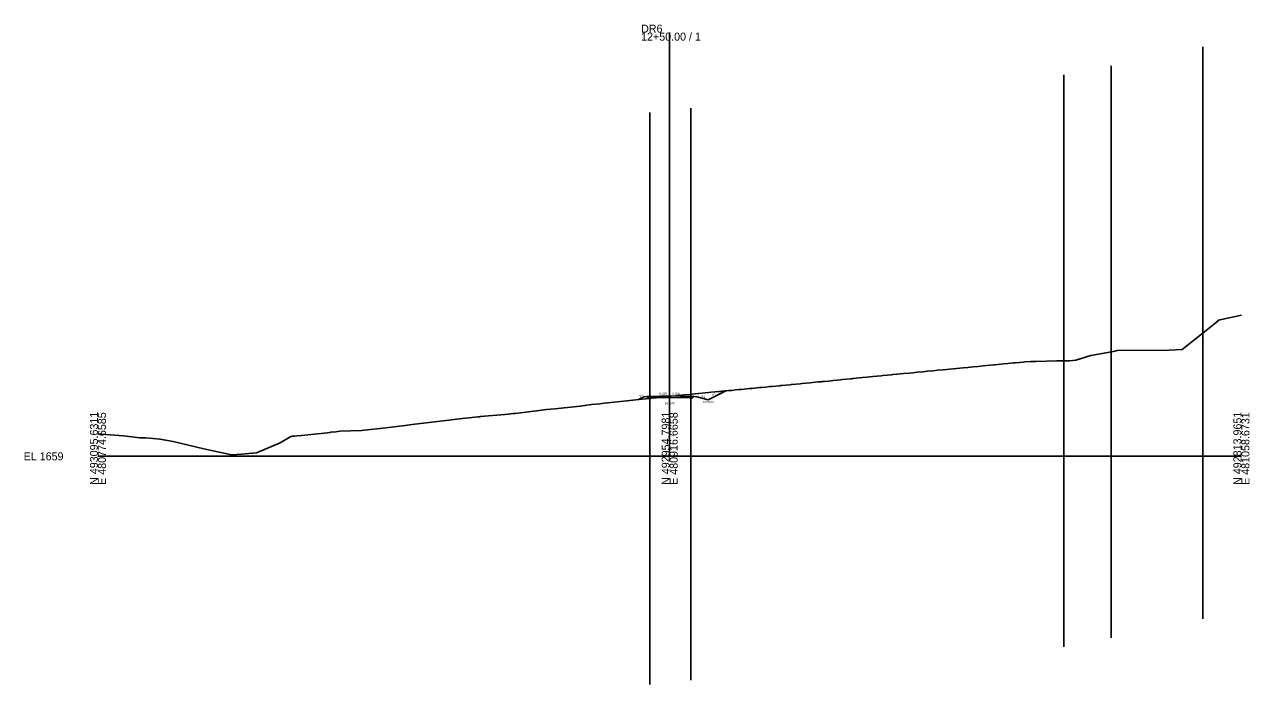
# Model space of a CAD drawing. Extents: x -26 to 403, y -88 to 5647.
# Drawn here: x -25.7 to 402.8, y 4920.2 to 5151 of the extents above; entities that cross this region are included whole.
import ezdxf

# ---------------------------------------------------------------- set-up
doc = ezdxf.new("R2010")
doc.units = 0
for name, color, linetype in [('Exist Cross Section Cell', 7, 'Continuous'), ('Exist XS Center Line Elevation Label', 7, 'Continuous'), ('Exist XS Ground Line', 7, 'Continuous'), ('Prop Road Sect_ Boring - Material (Outline)', 7, 'Continuous'), ('Prop XS Ditch Slope Text', 7, 'Continuous'), ('Prop XS Ditch Standard Text', 7, 'Continuous'), ('Prop XS Dump Level', 7, 'Continuous'), ('Prop XS Earthwork Shape', 7, 'Continuous'), ('Prop XS EOT Tick Mark', 7, 'Continuous'), ('Prop XS Finish Grade', 7, 'Continuous'), ('Prop XS Finish Grade Earthwork', 7, 'Continuous'), ('Prop XS Finish Grade Pavement', 7, 'Continuous'), ('Prop XS Hydro Typical Ditch Data', 7, 'Continuous'), ('Prop XS Pvmt Edge Slope', 7, 'Continuous'), ('Prop XS SE Text', 7, 'Continuous'), ('Prop XS Side Slope Text', 7, 'Continuous'), ('Prop XS Subgrade Earthwork', 7, 'Continuous'), ('Scratch_Level_7', 7, 'Continuous')]:
    doc.layers.add(name, color=color, linetype=linetype)

msp = doc.modelspace()

# ---------------------------------------------------------------- linework, layer by layer
at = {"layer": 'Exist Cross Section Cell'}
for p, q in [((200, 5000), (200, 5148.14)), ((0, 5000), (200, 5000)), ((200, 5000), (400, 5000))]:
    msp.add_line(p, q, dxfattribs=at)
at = {"layer": 'Exist XS Ground Line'}
msp.add_lwpolyline([(0, 5007.85), (2.77, 5007.6), (8.96, 5007.12), (14.66, 5006.5), (16.8, 5006.44), (21.67, 5006.03), (26.28, 5005.24), (37.04, 5002.65), (46.73, 5000.51), (47.11, 5000.53), (50.22, 5000.75), (51.5, 5000.84), (55.46, 5001.19), (63.72, 5004.67), (67.46, 5006.95), (67.96, 5007.04), (68.75, 5007.04), (69.71, 5007.13), (71.22, 5007.32), (80.3, 5008.27), (81.15, 5008.38), (81.52, 5008.42), (83.27, 5008.61), (84.6, 5008.77), (92.18, 5009.07), (100.71, 5010.02), (107.44, 5010.82), (109.92, 5011.15), (123.64, 5012.78), (125.39, 5012.97), (132.86, 5013.8), (133.18, 5013.83), (133.51, 5013.86), (133.83, 5013.9), (142.32, 5014.66), (143.66, 5014.79), (145.31, 5014.96), (146, 5015.02), (154.38, 5016.07), (156.97, 5016.32), (159.9, 5016.62), (163.1, 5016.94), (168.75, 5017.55), (172.61, 5018.11), (175.53, 5018.4), (177.09, 5018.56), (180.56, 5018.93), (185.05, 5019.4), (188.11, 5019.78), (189.32, 5019.88), (189.89, 5019.93), (190.29, 5019.97), (191.66, 5020.1), (193.08, 5020.23), (194.74, 5020.41), (196.98, 5020.63), (198.18, 5020.73), (199.42, 5020.88), (200, 5020.94), (200.56, 5021), (202.17, 5021.15), (202.98, 5021.24), (203.54, 5021.29), (204.06, 5021.36), (205.24, 5021.47), (207.16, 5021.66), (207.85, 5021.73), (208.9, 5021.84), (209.92, 5021.94), (210.25, 5021.98), (211.36, 5022.08), (212.45, 5022.18), (213.54, 5022.29), (214.56, 5022.39), (215.91, 5022.52), (217.21, 5022.64), (217.62, 5022.68), (218.14, 5022.73), (220.72, 5022.98), (221.72, 5023.07), (223.01, 5023.2), (224.29, 5023.32), (225.3, 5023.42), (227.83, 5023.67), (228.74, 5023.75), (231.43, 5024.02), (231.82, 5024.06), (232.25, 5024.1), (233.63, 5024.23), (234.98, 5024.36), (235.83, 5024.44), (238.52, 5024.7), (238.9, 5024.74), (239.28, 5024.78), (240.67, 5024.91), (242.04, 5025.04), (242.46, 5025.08), (242.89, 5025.12), (245.62, 5025.38), (246.35, 5025.45), (247.71, 5025.58), (249.16, 5025.72), (249.92, 5025.79), (252, 5025.99), (252.7, 5026.06), (253.05, 5026.09), (253.4, 5026.13), (254.14, 5026.2), (255.44, 5026.33), (256.46, 5026.43), (257.18, 5026.5), (258.63, 5026.64), (259.78, 5026.75), (260.48, 5026.82), (263.37, 5027.11), (263.68, 5027.14), (264.02, 5027.17), (267.49, 5027.52), (268.99, 5027.66), (271.02, 5027.87), (272.52, 5028.02), (274.02, 5028.16), (274.56, 5028.22), (276.06, 5028.37), (277.57, 5028.51), (278.08, 5028.56), (279.51, 5028.71), (281.83, 5028.94), (283.86, 5029.13), (285.11, 5029.25), (286.66, 5029.4), (288.62, 5029.59), (290.19, 5029.74), (292.13, 5029.94), (293.73, 5030.09), (295.65, 5030.28), (299.15, 5030.61), (302.69, 5030.96), (304.32, 5031.11), (306.19, 5031.29), (307.87, 5031.45), (309.72, 5031.64), (312.15, 5031.85), (313.36, 5031.98), (313.74, 5032.01), (314.77, 5032.11), (316.73, 5032.29), (318.33, 5032.45), (320.29, 5032.64), (320.92, 5032.71), (322.38, 5032.84), (323.79, 5032.98), (324.28, 5033.02), (326.38, 5033.17), (328.22, 5033.2), (335.38, 5033.35), (337.55, 5033.39), (339.21, 5033.42), (339.93, 5033.43), (342.06, 5033.58), (347.33, 5035.24), (353.31, 5036.27), (355.68, 5036.8), (356.2, 5036.91), (356.51, 5036.97), (374.69, 5037.12), (379.25, 5037.38), (390.58, 5046.3), (392.1, 5047.64), (392.43, 5047.68), (393.05, 5047.84), (400, 5049.38)], dxfattribs=at)
at = {"layer": 'Prop Road Sect_ Boring - Material (Outline)'}
for points in [[(193.01, 5020.97), (191.98, 5020.88), (192.45, 5020.41)], [(207.46, 5020.96), (208.49, 5020.87), (208.01, 5020.4)]]:
    msp.add_lwpolyline(points, close=True, dxfattribs=at)
at = {"layer": 'Prop XS Dump Level'}
for p, q in [((193.01, 5020.97), (200, 5021.11)), ((200, 5021.11), (207.46, 5020.96))]:
    msp.add_line(p, q, dxfattribs=at)
at = {"layer": 'Prop XS Earthwork Shape'}
for points in [[(195.39, 5020.47), (196.98, 5020.63), (198.18, 5020.73), (199.42, 5020.88), (200, 5020.94), (200.56, 5021), (202.17, 5021.15), (202.98, 5021.24), (203.54, 5021.29), (204.06, 5021.36), (205.24, 5021.47), (207.16, 5021.66), (207.85, 5021.73), (208.9, 5021.84), (209.92, 5021.94), (210.25, 5021.98), (211.36, 5022.08), (212.45, 5022.18), (213.54, 5022.29), (214.56, 5022.39), (215.91, 5022.52), (217.21, 5022.64), (217.62, 5022.68), (218.14, 5022.73), (219.61, 5022.87), (213.46, 5019.8), (209.46, 5020.8), (208.49, 5020.87), (208.01, 5020.4), (207.46, 5020.41), (200, 5020.56)], [(195.39, 5020.47), (193.01, 5020.42), (192.45, 5020.41), (191.98, 5020.88), (191.01, 5020.81), (189.12, 5019.86), (189.32, 5019.88), (189.89, 5019.93), (190.29, 5019.97), (191.66, 5020.1), (193.08, 5020.23), (194.74, 5020.41)]]:
    msp.add_lwpolyline(points, close=True, dxfattribs=at)
at = {"layer": 'Prop XS EOT Tick Mark'}
for p, q in [((193.01, 5020.97), (193.01, 5021.97)), ((207.46, 5020.96), (207.46, 5021.96))]:
    msp.add_line(p, q, dxfattribs=at)
at = {"layer": 'Prop XS Finish Grade'}
for p, q in [((193.01, 5020.97), (191.98, 5020.88)), ((207.46, 5020.96), (208.49, 5020.87))]:
    msp.add_line(p, q, dxfattribs=at)
at = {"layer": 'Prop XS Finish Grade Earthwork'}
for p, q in [((213.46, 5019.8), (219.61, 5022.87)), ((191.01, 5020.81), (189.12, 5019.86)), ((191.98, 5020.88), (191.01, 5020.81)), ((208.49, 5020.87), (209.46, 5020.8)), ((209.46, 5020.8), (213.46, 5019.8))]:
    msp.add_line(p, q, dxfattribs=at)
at = {"layer": 'Prop XS Finish Grade Pavement'}
for p, q in [((193.01, 5020.97), (200, 5021.11)), ((200, 5021.11), (207.46, 5020.96))]:
    msp.add_line(p, q, dxfattribs=at)
at = {"layer": 'Prop XS Hydro Typical Ditch Data'}
for p, q in [((209.46, 5020.8), (213.46, 5019.8)), ((213.46, 5019.8), (218.35, 5022.24))]:
    msp.add_line(p, q, dxfattribs=at)
at = {"layer": 'Prop XS Pvmt Edge Slope'}
for p, q in [((193.01, 5020.97), (192.45, 5020.41)), ((207.46, 5020.96), (208.01, 5020.4))]:
    msp.add_line(p, q, dxfattribs=at)
at = {"layer": 'Prop XS Subgrade Earthwork'}
for p, q in [((192.45, 5020.41), (191.98, 5020.88)), ((193.01, 5020.42), (192.45, 5020.41)), ((200, 5020.56), (193.01, 5020.42)), ((207.46, 5020.41), (200, 5020.56)), ((207.46, 5020.41), (208.01, 5020.4)), ((208.01, 5020.4), (208.49, 5020.87))]:
    msp.add_line(p, q, dxfattribs=at)
at = {"layer": 'Scratch_Level_7'}
for p, q in [((386.56, 5143.14), (386.56, 4943.14)), ((354.41, 5136.52), (354.41, 4936.52)), ((337.85, 5133.4), (337.85, 4933.4)), ((207.46, 5121.69), (207.46, 4921.69)), ((193.01, 5120.22), (193.01, 4920.22))]:
    msp.add_line(p, q, dxfattribs=at)

# ---------------------------------------------------------------- texts
at = {"layer": 'Exist Cross Section Cell'}
for s, p in [('DR6', (190, 5148.14)), ('12+50.00 / 1', (190, 5145.34)), ('EL 1659', (-26, 4998.6))]:
    msp.add_text(s, height=2.8, dxfattribs=at).set_placement(p)
for s, p in [('N 493095.6311', (0, 4990)), ('E 480774.6585', (2.8, 4990)), ('N 492954.7981', (200, 4990)), ('E 480916.6658', (202.8, 4990)), ('N 492813.9651', (400, 4990)), ('E 481058.6731', (402.8, 4990))]:
    msp.add_text(s, height=2.8, rotation=90, dxfattribs=at).set_placement(p)
at = {"layer": 'Exist XS Center Line Elevation Label'}
msp.add_text('1679.94', height=0.75, dxfattribs=at).set_placement((198.31, 5018.19))
at = {"layer": 'Prop XS Ditch Slope Text'}
for s, rotation, p in [('2:1', 26.5651, (189.64, 5020.61)), ('4:1', 345.9638, (211, 5020.71))]:
    msp.add_text(s, height=0.75, rotation=rotation, dxfattribs=at).set_placement(p)
at = {"layer": 'Prop XS Ditch Standard Text'}
msp.add_text('1678.80', height=0.75, dxfattribs=at).set_placement((211.65, 5018.61))
at = {"layer": 'Prop XS Dump Level'}
for p in [(191.01, 5020.77), (209.46, 5020.76)]:
    msp.add_text('Case1', height=0.04, dxfattribs=at).set_placement(p)
at = {"layer": 'Prop XS SE Text'}
for rotation, p in [(1.1458, (196.44, 5021.53)), (358.8542, (200.94, 5021.59))]:
    msp.add_text('0.020', height=0.75, rotation=rotation, dxfattribs=at).set_placement(p)
at = {"layer": 'Prop XS Side Slope Text'}
msp.add_text('2:1', height=0.75, rotation=26.5651, dxfattribs=at).set_placement((215.01, 5020.94))

doc.saveas('drawing.dxf')
